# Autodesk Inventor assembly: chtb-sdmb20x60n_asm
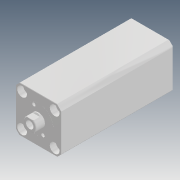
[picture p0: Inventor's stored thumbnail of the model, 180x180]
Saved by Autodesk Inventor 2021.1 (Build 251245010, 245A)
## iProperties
Company: Microsoft
Created: 2018-05
Part Number: chtb-sdmb20x60n_asm
Description: STEP AP214
Document SubType Name: Assembly
Designer: user
Title: chtb-sdmb20x60n_asm.STEP
Author: Windows
Revision Number: ÈÎºÎ
Sending System: SolidWorks 2015
Preprocessor: SwSTEP 2.0
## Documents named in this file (4)
- D:\Vault_2016\Projekty\Clamptek\Hydraulic\CHTB\CHTB-20\Inventor\CHTB-SDMB20x60N\chtb-sdmb20x60n_asm.iam
- D:\Vault_2016\Projekty\Clamptek\Hydraulic\CHTB\CHTB-20\Inventor\CHTB-SDMB20x60N\CHTB-SDMB20X60NBT.ipt
- D:\Vault_2016\Projekty\Clamptek\Hydraulic\CHTB\CHTB-20\Inventor\CHTB-SDMB20x60N\CHTB-SDMB20X60NHSG.ipt
- D:\Vault_2016\Projekty\Clamptek\Hydraulic\CHTB\CHTB-20\Inventor\CHTB-SDMB20x60N\QG_3.ipt
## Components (3 placed, 3 different names)
1. CHTB-SDMB20X60NBT_1
2. CHTB-SDMB20X60NHSG_2
3. QG_3_3
